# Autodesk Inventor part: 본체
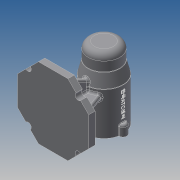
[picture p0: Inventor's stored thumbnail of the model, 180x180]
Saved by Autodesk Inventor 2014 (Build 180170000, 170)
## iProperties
Created: 2019-12
Part Number: 본체
Material: Generic
Document SubType Name: Modeling
Designer: kb542-15
Density: 1 g/cm^3
Appearance: Default
Author: kb542-15
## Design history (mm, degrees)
sketch "스케치1"
  geometry: L1 (0, 0)-(36, 0); L2 (0, 0)-(-36, 0); L3 (-36, 0)-(-10.522, 70); L4 (-36, 0)-(59.856, 0); L5 (36, 0)-(10.522, 70); L6 (36, 0)-(130.15, 0); L7 (0, 70)-(10.522, 70); L8 (10.522, 70)-(-10.522, 70)
  constraints: 16 end point, 3 horizontal, 2 collinear
  dimensions: "d0" = 36 distance of L1.start L1.end; "d1" = 36 distance of L1.start L2.end; "d2" = 70 deg angle of L4 L3; "d3" = 110 deg angle of L6 L5
extrude "돌출1" new body sketch "스케치1" stored distance "d5" = 8; taper "d6" = 0 deg
sketch "스케치2"
  geometry: L1 (0, 0)-(0, 38); L2 (0, 38)-(70, 5.358); L3 (0, 0)-(0, -31); L4 (0, -31)-(70, -31); L5 (70, -31)-(70, 5.358)
  constraints: 10 end point, 1 collinear, 1 perpendicular, 1 vertical
  dimensions: "d7" = 38 distance of L1.start L1.end; "d8" = 65 deg angle of L1 L2; "d9" = 31 distance of L1.start L3.end; "d10" = 70 distance of L3.end L4.end
extrude "돌출2" join sketch "스케치2" stored distance "d11" = 8; taper "d12" = 0 deg
sketch "스케치3"
  geometry: L1 (20, -19.196)-(-12.804, -52); L2 (-12.804, -52)-(-59.196, -52); L3 (-59.196, -52)-(-92, -19.196); L4 (-92, -19.196)-(-92, 27.196); L5 (-92, 27.196)-(-59.196, 60); L6 (-59.196, 60)-(-12.804, 60); L7 (-12.804, 60)-(20, 27.196); L8 (20, 27.196)-(20, -19.196); 4 further points
  constraints: 16 end point, 1 coincident, 1 horizontal alignment, 1 midpoint, 19 other
extrude "돌출3" join sketch "스케치3" distance "d14" = 10; taper "d15" = 0 deg
revolve "회전1" stored, may be unused: angle "d27" = 90 deg
sketch "스케치5"
  geometry: C1 r 6 at (0, 30); C2 r 6 at (30, 0); C3 r 6 at (0, -30); C4 r 6 at (-30, 0); A1 r 30 centre (0, 0) between (0, 30) and (30, 0) reference; 1 further point
  constraints: 4 centre point, 4 point on circle
  dimensions: "d28" = 12 diameter of C1; "d29" = 12 diameter of C2; "d30" = 12 diameter of C3; "d31" = 12 diameter of C4
extrude "돌출4" join sketch "스케치5" distance "d32" = 16; taper "d33" = 0 deg
sketch "스케치6"
  geometry: C1 r 21 at (0, 30); A1 r 30 centre (0, 30) between (-5.97, 59.4) and (-29.4, 35.97) reference; 1 further point
  constraints: 1 centre point, 1 coincident
  dimensions: "d34" = 42 diameter of C1
extrude "돌출5" cut sketch "스케치6" distance "d35" = 15; taper "d36" = 0 deg
sketch "스케치7"
  geometry: C1 r 21 at (0, 0) reference; C2 r 24 at (0, 0); 1 further point
  constraints: 1 centre point, 1 coincident
  dimensions: "d37" = 48 diameter of C2
extrude "돌출6" cut sketch "스케치7" distance "d38" = 54; taper "d39" = 0 deg
sketch "스케치8"
  geometry: C1 r 24 at (0, 0) reference; C2 r 21 at (0, 0); 1 further point
  constraints: 1 centre point, 1 coincident
  dimensions: "d40" = 42 diameter of C2
extrude "돌출7" cut sketch "스케치8" distance "d41" = 12; taper "d42" = 0 deg
sketch "스케치9"
  geometry: C1 r 21 at (0, 0) reference; C2 r 17.5 at (0, 0); 1 further point
  constraints: 1 centre point, 1 coincident
  dimensions: "d43" = 35 diameter of C2
extrude "돌출8" cut sketch "스케치9" distance "d44" = 18; taper "d45" = 0 deg
sketch "스케치10"
  geometry: C1 r 17.5 at (0, 0) reference; C2 r 16 at (0, 0); 1 further point
  constraints: 1 centre point, 1 coincident
  dimensions: "d46" = 32 diameter of C2
extrude "돌출9" cut sketch "스케치10" distance "d47" = 4; taper "d48" = 0 deg
sketch "스케치11"
  geometry: C1 r 16 at (0, 0) reference; C2 r 10.5 at (0, 0); 1 further point
  constraints: 1 centre point, 1 coincident
  dimensions: "d49" = 21 diameter of C2
extrude "돌출10" cut sketch "스케치11" distance "d50" = 3; taper "d51" = 0 deg
sketch "스케치12"
  geometry: L1 (-36, -4)-(20, -4); 4 further points
  constraints: 2 end point, 1 horizontal
hole "구멍1" sketch "스케치12" at (-75.598, 35.598), (-75.598, -43.598), (3.598, -43.598), (3.598, 35.598) diameter "d53" = 10; stored, may be unused: countersink angle "d57" = 90 deg, drill point angle "d59" = 118 deg; dims "d54" = 6, "d55" = 4, "d56" = 2, "d58" = 8
sketch "스케치13"
  geometry: A1 r 6 centre (0, 0) between (-5.97, 0.6) and (5.97, 0.6) reference; A2 r 6 centre (30, 30) between (29.4, 24.03) and (29.4, 35.97) reference; A3 r 6 centre (0, 60) between (5.97, 59.4) and (-5.97, 59.4) reference; A4 r 6 centre (-30, 30) between (-29.4, 35.97) and (-29.4, 24.03) reference; 5 further points
  constraints: 4 coincident
hole "구멍2" sketch "스케치13" at (0, 60), (30, 30), (0, 0), (-30, 30) diameter "d60" = 3.242; stored, may be unused: countersink angle "d64" = 90 deg, drill point angle "d66" = 118 deg; dims "d61" = 8, "d62" = 4, "d63" = 2, "d65" = 11
fillet "모깎기1" dims "d67" = 0.3
fillet "모깎기2" dims "d68" = 3
fillet "모깎기3" dims "d69" = 3
chamfer "모따기1" distance "d70" = 1; stored, may be unused: second distance "d71" = 2, angle "d72" = 45 deg
fillet "모깎기4" dims "d73" = 10
fillet "모깎기5" dims "d74" = 3
fillet "모깎기6" dims "d75" = 3
fillet "모깎기8" dims "d77" = 3
fillet "모깎기9" dims "d78" = 3
fillet "모깎기10" dims "d79" = 1
fillet "모깎기11" dims "d80" = 3
fillet "모깎기12" dims "d81" = 3
node "작업 평면1"
sketch "스케치14"
  geometry: L1 (73.002, 5.739)-(73.002, -35.739); L2 (73.002, -35.739)-(66.998, -35.739); L3 (66.998, -35.739)-(66.998, 5.739); L4 (66.998, 5.739)-(73.002, 5.739); L5 (0, -56)-(-10, -56) reference; 1 further point
  constraints: 2 other
feature "엠보싱1" sketch "스케치14" dims "d0" = 36, "d1" = 36, "d2" = 70 deg, "d3" = 110 deg, "d87" = 0.5, "d88" = 0
node "솔리드1"
sketch "스케치4"
  geometry: L1 (-10, 0)-(70, 0); L2 (70, 0)-(70, -56); L3 (70, 0)-(70, 56); L4 (70, 56)-(95, 56); L5 (95, 56)-(95, 31); L6 (100, 11)-(95, 31); L7 (70, -56)-(100, -56); L8 (100, -56)-(100, 11); 1 further point
  constraints: 16 end point, 4 perpendicular, 1 collinear
  dimensions: "d22" = 25 distance of L3.end L4.end; "d23" = 25 distance of L4.end L5.end; "d26" = 30 distance of L2.end L7.end
other parameters: "d82" = 30.5
